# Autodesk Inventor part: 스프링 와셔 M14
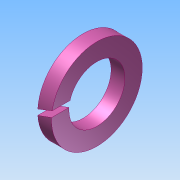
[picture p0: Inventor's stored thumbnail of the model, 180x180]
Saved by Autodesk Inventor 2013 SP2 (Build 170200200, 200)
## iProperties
Created: 2025-08
Part Number: 스프링 와셔 M14
Material: Generic
Document SubType Name: Modeling
Designer: i
Density: 1 g/cm^3
Author: i
변환 표준: STEP AP214IS
전처리기: Build: 200, Release: 2013 SP2 Update 6 - Date: Thu 07/17/2014
전송 단위: 밀리미터
불확실성: 0.01
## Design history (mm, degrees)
node "스프링 와셔 M141"
body "Solid1"
node "기준1"
